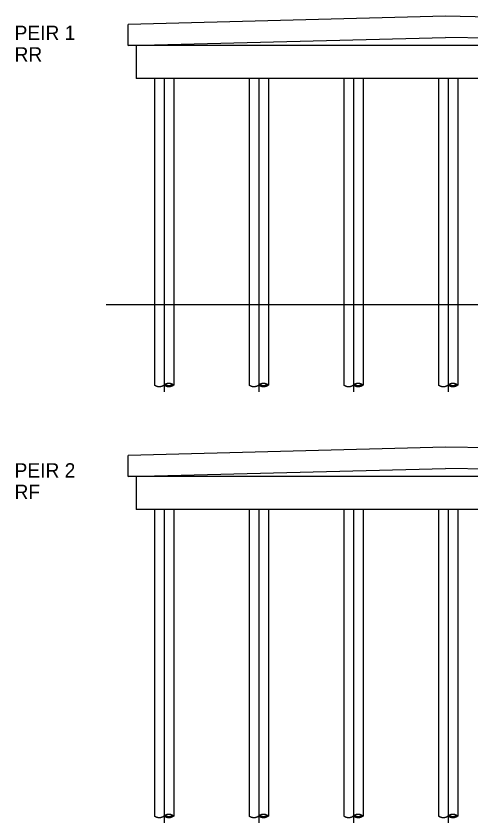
# Model space of a CAD drawing. Extents: x -8 to 159, y -47 to 10.
# Drawn here: x -7.56 to 20.06, y -47.01 to 1.94 of the extents above; entities that cross this region are included whole.
import ezdxf

# ---------------------------------------------------------------- set-up
doc = ezdxf.new("R2010")
doc.units = 0
for name, color, linetype in [('BR_X_Gen_Ground_Slope', 7, 'Continuous'), ('BR_X_Slab_Const_Joint', 7, 'Continuous'), ('BR_X_Slab_Object', 7, 'Continuous'), ('BR_X_Sub_Deep_Centerline', 7, 'Continuous'), ('BR_X_Sub_Object', 7, 'Continuous'), ('HY_P_Water_Edge', 7, 'Continuous')]:
    doc.layers.add(name, color=color, linetype=linetype)

msp = doc.modelspace()

# ---------------------------------------------------------------- linework, layer by layer
at = {"layer": 'BR_X_Gen_Ground_Slope'}
msp.add_line((1.427, -15.771), (1.427, -16.271), dxfattribs=at)
at = {"layer": 'BR_X_Slab_Const_Joint'}
for p, q in [((43.365, 0.146), (-0.26, 0.146)), ((43.365, -26), (-0.26, -26))]:
    msp.add_line(p, q, dxfattribs=at)
at = {"layer": 'BR_X_Slab_Object'}
for p, q in [((18.51, 1.937), (-0.76, 1.437)), ((43.865, 1.437), (18.51, 1.937)), ((-0.76, 0.146), (-0.76, 1.437)), ((-0.76, 0.146), (18.51, 0.646)), ((43.865, 0.146), (18.51, 0.646)), ((-0.26, 0.146), (-0.76, 0.146)), ((18.51, -24.208), (-0.76, -24.708)), ((43.865, -24.708), (18.51, -24.208)), ((-0.76, -26), (-0.76, -24.708)), ((-0.76, -26), (18.51, -25.5)), ((43.865, -26), (18.51, -25.5)), ((-0.26, -26), (-0.76, -26))]:
    msp.add_line(p, q, dxfattribs=at)
at = {"layer": 'BR_X_Sub_Deep_Centerline'}
for p, q in [((1.427, -1.854), (1.427, -20.859)), ((7.177, -1.854), (7.177, -20.859)), ((12.927, -1.854), (12.927, -20.859)), ((18.677, -1.854), (18.677, -20.859)), ((1.427, -28), (1.427, -47.005)), ((7.177, -28), (7.177, -47.005)), ((12.927, -28), (12.927, -47.005)), ((18.677, -28), (18.677, -47.005))]:
    msp.add_line(p, q, dxfattribs=at)
at = {"layer": 'BR_X_Sub_Object'}
for p, q in [((-0.26, 0.146), (-0.26, -1.854)), ((43.365, -1.854), (-0.26, -1.854)), ((0.844, -1.854), (0.844, -20.447)), ((2.011, -1.854), (2.011, -20.447)), ((6.594, -1.854), (6.594, -20.447)), ((7.761, -1.854), (7.761, -20.447)), ((12.344, -1.854), (12.344, -20.447)), ((13.511, -1.854), (13.511, -20.447)), ((18.094, -1.854), (18.094, -20.447)), ((19.261, -1.854), (19.261, -20.447)), ((-0.26, -26), (-0.26, -28)), ((43.365, -28), (-0.26, -28)), ((0.844, -28), (0.844, -46.593)), ((2.011, -28), (2.011, -46.593)), ((6.594, -28), (6.594, -46.593)), ((7.761, -28), (7.761, -46.593)), ((12.344, -28), (12.344, -46.593)), ((13.511, -28), (13.511, -46.593)), ((18.094, -28), (18.094, -46.593)), ((19.261, -28), (19.261, -46.593))]:
    msp.add_line(p, q, dxfattribs=at)
for points in [[(2.011, -20.447), (1.953, -20.407), (1.841, -20.361), (1.76, -20.347), (1.718, -20.345), (1.69, -20.346), (1.641, -20.352), (1.601, -20.36), (1.574, -20.368), (1.53, -20.385), (1.494, -20.402), (1.467, -20.419), (1.453, -20.428), (1.438, -20.439), (1.427, -20.447), (1.408, -20.463), (1.394, -20.473), (1.383, -20.48), (1.369, -20.489), (1.346, -20.502), (1.317, -20.516), (1.3, -20.523), (1.271, -20.533), (1.239, -20.542), (1.224, -20.545), (1.202, -20.549), (1.181, -20.552), (1.157, -20.554), (1.137, -20.554), (1.096, -20.552), (1.064, -20.548), (1.032, -20.542), (1.008, -20.536), (0.984, -20.528), (0.965, -20.52), (0.944, -20.511), (0.921, -20.5), (0.903, -20.49), (0.885, -20.478), (0.864, -20.463), (0.856, -20.457), (0.844, -20.447)], [(2.011, -20.447), (1.995, -20.46), (1.975, -20.475), (1.954, -20.488), (1.932, -20.501), (1.916, -20.509), (1.891, -20.52), (1.867, -20.529), (1.839, -20.538), (1.81, -20.545), (1.787, -20.549), (1.766, -20.552), (1.747, -20.553), (1.714, -20.554), (1.685, -20.554), (1.664, -20.551), (1.638, -20.547), (1.601, -20.538), (1.572, -20.529), (1.545, -20.519), (1.521, -20.508), (1.506, -20.5), (1.483, -20.487), (1.464, -20.475), (1.45, -20.465), (1.441, -20.458), (1.427, -20.447)], [(1.949, -20.41), (1.93, -20.424), (1.906, -20.438), (1.893, -20.445), (1.878, -20.453), (1.857, -20.462), (1.835, -20.469), (1.822, -20.474), (1.797, -20.48), (1.783, -20.483), (1.763, -20.486), (1.741, -20.488), (1.716, -20.489), (1.723, -20.489), (1.705, -20.489), (1.692, -20.488), (1.669, -20.486), (1.64, -20.482), (1.623, -20.478), (1.602, -20.472), (1.588, -20.468), (1.568, -20.46), (1.557, -20.456), (1.548, -20.451), (1.537, -20.446), (1.525, -20.439), (1.514, -20.433), (1.496, -20.422), (1.491, -20.418), (1.481, -20.41)], [(7.761, -20.447), (7.703, -20.407), (7.591, -20.361), (7.51, -20.347), (7.468, -20.345), (7.44, -20.346), (7.391, -20.352), (7.351, -20.36), (7.324, -20.368), (7.28, -20.385), (7.244, -20.402), (7.217, -20.419), (7.203, -20.428), (7.188, -20.439), (7.177, -20.447), (7.158, -20.463), (7.144, -20.473), (7.133, -20.48), (7.119, -20.489), (7.096, -20.502), (7.067, -20.516), (7.05, -20.523), (7.021, -20.533), (6.989, -20.542), (6.974, -20.545), (6.952, -20.549), (6.931, -20.552), (6.907, -20.554), (6.887, -20.554), (6.846, -20.552), (6.814, -20.548), (6.782, -20.542), (6.758, -20.536), (6.734, -20.528), (6.715, -20.52), (6.694, -20.511), (6.671, -20.5), (6.653, -20.49), (6.635, -20.478), (6.614, -20.463), (6.606, -20.457), (6.594, -20.447)], [(7.761, -20.447), (7.745, -20.46), (7.725, -20.475), (7.704, -20.488), (7.682, -20.501), (7.666, -20.509), (7.641, -20.52), (7.617, -20.529), (7.589, -20.538), (7.56, -20.545), (7.537, -20.549), (7.516, -20.552), (7.497, -20.553), (7.464, -20.554), (7.435, -20.554), (7.414, -20.551), (7.388, -20.547), (7.351, -20.538), (7.322, -20.529), (7.295, -20.519), (7.271, -20.508), (7.256, -20.5), (7.233, -20.487), (7.214, -20.475), (7.2, -20.465), (7.191, -20.458), (7.177, -20.447)], [(7.699, -20.41), (7.68, -20.424), (7.656, -20.438), (7.643, -20.445), (7.628, -20.453), (7.607, -20.462), (7.585, -20.469), (7.572, -20.474), (7.547, -20.48), (7.533, -20.483), (7.513, -20.486), (7.491, -20.488), (7.466, -20.489), (7.473, -20.489), (7.455, -20.489), (7.442, -20.488), (7.419, -20.486), (7.39, -20.482), (7.373, -20.478), (7.352, -20.472), (7.338, -20.468), (7.318, -20.46), (7.307, -20.456), (7.298, -20.451), (7.287, -20.446), (7.275, -20.439), (7.264, -20.433), (7.246, -20.422), (7.241, -20.418), (7.231, -20.41)], [(13.511, -20.447), (13.453, -20.407), (13.341, -20.361), (13.26, -20.347), (13.218, -20.345), (13.19, -20.346), (13.141, -20.352), (13.101, -20.36), (13.074, -20.368), (13.03, -20.385), (12.994, -20.402), (12.967, -20.419), (12.953, -20.428), (12.938, -20.439), (12.927, -20.447), (12.908, -20.463), (12.894, -20.473), (12.883, -20.48), (12.869, -20.489), (12.846, -20.502), (12.817, -20.516), (12.8, -20.523), (12.771, -20.533), (12.739, -20.542), (12.724, -20.545), (12.702, -20.549), (12.681, -20.552), (12.657, -20.554), (12.637, -20.554), (12.596, -20.552), (12.564, -20.548), (12.532, -20.542), (12.508, -20.536), (12.484, -20.528), (12.465, -20.52), (12.444, -20.511), (12.421, -20.5), (12.403, -20.49), (12.385, -20.478), (12.364, -20.463), (12.356, -20.457), (12.344, -20.447)], [(13.511, -20.447), (13.495, -20.46), (13.475, -20.475), (13.454, -20.488), (13.432, -20.501), (13.416, -20.509), (13.391, -20.52), (13.367, -20.529), (13.339, -20.538), (13.31, -20.545), (13.287, -20.549), (13.266, -20.552), (13.247, -20.553), (13.214, -20.554), (13.185, -20.554), (13.164, -20.551), (13.138, -20.547), (13.101, -20.538), (13.072, -20.529), (13.045, -20.519), (13.021, -20.508), (13.006, -20.5), (12.983, -20.487), (12.964, -20.475), (12.95, -20.465), (12.941, -20.458), (12.927, -20.447)], [(13.449, -20.41), (13.43, -20.424), (13.406, -20.438), (13.393, -20.445), (13.378, -20.453), (13.357, -20.462), (13.335, -20.469), (13.322, -20.474), (13.297, -20.48), (13.283, -20.483), (13.263, -20.486), (13.241, -20.488), (13.216, -20.489), (13.223, -20.489), (13.205, -20.489), (13.192, -20.488), (13.169, -20.486), (13.14, -20.482), (13.123, -20.478), (13.102, -20.472), (13.088, -20.468), (13.068, -20.46), (13.057, -20.456), (13.048, -20.451), (13.037, -20.446), (13.025, -20.439), (13.014, -20.433), (12.996, -20.422), (12.991, -20.418), (12.981, -20.41)], [(19.261, -20.447), (19.203, -20.407), (19.091, -20.361), (19.01, -20.347), (18.968, -20.345), (18.94, -20.346), (18.891, -20.352), (18.851, -20.36), (18.824, -20.368), (18.78, -20.385), (18.744, -20.402), (18.717, -20.419), (18.703, -20.428), (18.688, -20.439), (18.677, -20.447), (18.658, -20.463), (18.644, -20.473), (18.633, -20.48), (18.619, -20.489), (18.596, -20.502), (18.567, -20.516), (18.55, -20.523), (18.521, -20.533), (18.489, -20.542), (18.474, -20.545), (18.452, -20.549), (18.431, -20.552), (18.407, -20.554), (18.387, -20.554), (18.346, -20.552), (18.314, -20.548), (18.282, -20.542), (18.258, -20.536), (18.234, -20.528), (18.215, -20.52), (18.194, -20.511), (18.171, -20.5), (18.153, -20.49), (18.135, -20.478), (18.114, -20.463), (18.106, -20.457), (18.094, -20.447)], [(19.261, -20.447), (19.245, -20.46), (19.225, -20.475), (19.204, -20.488), (19.182, -20.501), (19.166, -20.509), (19.141, -20.52), (19.117, -20.529), (19.089, -20.538), (19.06, -20.545), (19.037, -20.549), (19.016, -20.552), (18.997, -20.553), (18.964, -20.554), (18.935, -20.554), (18.914, -20.551), (18.888, -20.547), (18.851, -20.538), (18.822, -20.529), (18.795, -20.519), (18.771, -20.508), (18.756, -20.5), (18.733, -20.487), (18.714, -20.475), (18.7, -20.465), (18.691, -20.458), (18.677, -20.447)], [(19.199, -20.41), (19.18, -20.424), (19.156, -20.438), (19.143, -20.445), (19.128, -20.453), (19.107, -20.462), (19.085, -20.469), (19.072, -20.474), (19.047, -20.48), (19.033, -20.483), (19.013, -20.486), (18.991, -20.488), (18.966, -20.489), (18.973, -20.489), (18.955, -20.489), (18.942, -20.488), (18.919, -20.486), (18.89, -20.482), (18.873, -20.478), (18.852, -20.472), (18.838, -20.468), (18.818, -20.46), (18.807, -20.456), (18.798, -20.451), (18.787, -20.446), (18.775, -20.439), (18.764, -20.433), (18.746, -20.422), (18.741, -20.418), (18.731, -20.41)], [(2.011, -46.593), (1.953, -46.553), (1.841, -46.507), (1.76, -46.492), (1.718, -46.491), (1.69, -46.492), (1.641, -46.497), (1.601, -46.506), (1.574, -46.514), (1.53, -46.531), (1.494, -46.548), (1.467, -46.565), (1.453, -46.574), (1.438, -46.585), (1.427, -46.592), (1.408, -46.609), (1.394, -46.618), (1.383, -46.626), (1.369, -46.635), (1.346, -46.648), (1.317, -46.662), (1.3, -46.669), (1.271, -46.679), (1.239, -46.688), (1.224, -46.691), (1.202, -46.695), (1.181, -46.698), (1.157, -46.699), (1.137, -46.7), (1.096, -46.698), (1.064, -46.694), (1.032, -46.688), (1.008, -46.681), (0.984, -46.673), (0.965, -46.666), (0.944, -46.657), (0.921, -46.645), (0.903, -46.635), (0.885, -46.624), (0.864, -46.609), (0.856, -46.602), (0.844, -46.593)], [(7.761, -46.593), (7.703, -46.553), (7.591, -46.507), (7.51, -46.492), (7.468, -46.491), (7.44, -46.492), (7.391, -46.497), (7.351, -46.506), (7.324, -46.514), (7.28, -46.531), (7.244, -46.548), (7.217, -46.565), (7.203, -46.574), (7.188, -46.585), (7.177, -46.592), (7.158, -46.609), (7.144, -46.618), (7.133, -46.626), (7.119, -46.635), (7.096, -46.648), (7.067, -46.662), (7.05, -46.669), (7.021, -46.679), (6.989, -46.688), (6.974, -46.691), (6.952, -46.695), (6.931, -46.698), (6.907, -46.699), (6.887, -46.7), (6.846, -46.698), (6.814, -46.694), (6.782, -46.688), (6.758, -46.681), (6.734, -46.673), (6.715, -46.666), (6.694, -46.657), (6.671, -46.645), (6.653, -46.635), (6.635, -46.624), (6.614, -46.609), (6.606, -46.602), (6.594, -46.593)], [(13.511, -46.593), (13.453, -46.553), (13.341, -46.507), (13.26, -46.492), (13.218, -46.491), (13.19, -46.492), (13.141, -46.497), (13.101, -46.506), (13.074, -46.514), (13.03, -46.531), (12.994, -46.548), (12.967, -46.565), (12.953, -46.574), (12.938, -46.585), (12.927, -46.592), (12.908, -46.609), (12.894, -46.618), (12.883, -46.626), (12.869, -46.635), (12.846, -46.648), (12.817, -46.662), (12.8, -46.669), (12.771, -46.679), (12.739, -46.688), (12.724, -46.691), (12.702, -46.695), (12.681, -46.698), (12.657, -46.699), (12.637, -46.7), (12.596, -46.698), (12.564, -46.694), (12.532, -46.688), (12.508, -46.681), (12.484, -46.673), (12.465, -46.666), (12.444, -46.657), (12.421, -46.645), (12.403, -46.635), (12.385, -46.624), (12.364, -46.609), (12.356, -46.602), (12.344, -46.593)], [(19.261, -46.593), (19.203, -46.553), (19.091, -46.507), (19.01, -46.492), (18.968, -46.491), (18.94, -46.492), (18.891, -46.497), (18.851, -46.506), (18.824, -46.514), (18.78, -46.531), (18.744, -46.548), (18.717, -46.565), (18.703, -46.574), (18.688, -46.585), (18.677, -46.592), (18.658, -46.609), (18.644, -46.618), (18.633, -46.626), (18.619, -46.635), (18.596, -46.648), (18.567, -46.662), (18.55, -46.669), (18.521, -46.679), (18.489, -46.688), (18.474, -46.691), (18.452, -46.695), (18.431, -46.698), (18.407, -46.699), (18.387, -46.7), (18.346, -46.698), (18.314, -46.694), (18.282, -46.688), (18.258, -46.681), (18.234, -46.673), (18.215, -46.666), (18.194, -46.657), (18.171, -46.645), (18.153, -46.635), (18.135, -46.624), (18.114, -46.609), (18.106, -46.602), (18.094, -46.593)], [(2.011, -46.593), (1.995, -46.605), (1.975, -46.62), (1.954, -46.634), (1.932, -46.646), (1.916, -46.655), (1.891, -46.666), (1.867, -46.675), (1.839, -46.684), (1.81, -46.691), (1.787, -46.695), (1.766, -46.697), (1.747, -46.699), (1.714, -46.7), (1.685, -46.7), (1.664, -46.696), (1.638, -46.692), (1.601, -46.684), (1.572, -46.675), (1.545, -46.665), (1.521, -46.654), (1.506, -46.646), (1.483, -46.633), (1.464, -46.621), (1.45, -46.61), (1.441, -46.604), (1.427, -46.593)], [(1.949, -46.556), (1.93, -46.57), (1.906, -46.584), (1.893, -46.591), (1.878, -46.599), (1.857, -46.608), (1.835, -46.615), (1.822, -46.62), (1.797, -46.626), (1.783, -46.629), (1.763, -46.632), (1.741, -46.634), (1.716, -46.635), (1.723, -46.634), (1.705, -46.634), (1.692, -46.634), (1.669, -46.632), (1.64, -46.627), (1.623, -46.624), (1.602, -46.618), (1.588, -46.613), (1.568, -46.606), (1.557, -46.601), (1.548, -46.597), (1.537, -46.592), (1.525, -46.585), (1.514, -46.579), (1.496, -46.568), (1.491, -46.564), (1.481, -46.556)], [(7.761, -46.593), (7.745, -46.605), (7.725, -46.62), (7.704, -46.634), (7.682, -46.646), (7.666, -46.655), (7.641, -46.666), (7.617, -46.675), (7.589, -46.684), (7.56, -46.691), (7.537, -46.695), (7.516, -46.697), (7.497, -46.699), (7.464, -46.7), (7.435, -46.7), (7.414, -46.696), (7.388, -46.692), (7.351, -46.684), (7.322, -46.675), (7.295, -46.665), (7.271, -46.654), (7.256, -46.646), (7.233, -46.633), (7.214, -46.621), (7.2, -46.61), (7.191, -46.604), (7.177, -46.593)], [(7.699, -46.556), (7.68, -46.57), (7.656, -46.584), (7.643, -46.591), (7.628, -46.599), (7.607, -46.608), (7.585, -46.615), (7.572, -46.62), (7.547, -46.626), (7.533, -46.629), (7.513, -46.632), (7.491, -46.634), (7.466, -46.635), (7.473, -46.634), (7.455, -46.634), (7.442, -46.634), (7.419, -46.632), (7.39, -46.627), (7.373, -46.624), (7.352, -46.618), (7.338, -46.613), (7.318, -46.606), (7.307, -46.601), (7.298, -46.597), (7.287, -46.592), (7.275, -46.585), (7.264, -46.579), (7.246, -46.568), (7.241, -46.564), (7.231, -46.556)], [(13.511, -46.593), (13.495, -46.605), (13.475, -46.62), (13.454, -46.634), (13.432, -46.646), (13.416, -46.655), (13.391, -46.666), (13.367, -46.675), (13.339, -46.684), (13.31, -46.691), (13.287, -46.695), (13.266, -46.697), (13.247, -46.699), (13.214, -46.7), (13.185, -46.7), (13.164, -46.696), (13.138, -46.692), (13.101, -46.684), (13.072, -46.675), (13.045, -46.665), (13.021, -46.654), (13.006, -46.646), (12.983, -46.633), (12.964, -46.621), (12.95, -46.61), (12.941, -46.604), (12.927, -46.593)], [(13.449, -46.556), (13.43, -46.57), (13.406, -46.584), (13.393, -46.591), (13.378, -46.599), (13.357, -46.608), (13.335, -46.615), (13.322, -46.62), (13.297, -46.626), (13.283, -46.629), (13.263, -46.632), (13.241, -46.634), (13.216, -46.635), (13.223, -46.634), (13.205, -46.634), (13.192, -46.634), (13.169, -46.632), (13.14, -46.627), (13.123, -46.624), (13.102, -46.618), (13.088, -46.613), (13.068, -46.606), (13.057, -46.601), (13.048, -46.597), (13.037, -46.592), (13.025, -46.585), (13.014, -46.579), (12.996, -46.568), (12.991, -46.564), (12.981, -46.556)], [(19.261, -46.593), (19.245, -46.605), (19.225, -46.62), (19.204, -46.634), (19.182, -46.646), (19.166, -46.655), (19.141, -46.666), (19.117, -46.675), (19.089, -46.684), (19.06, -46.691), (19.037, -46.695), (19.016, -46.697), (18.997, -46.699), (18.964, -46.7), (18.935, -46.7), (18.914, -46.696), (18.888, -46.692), (18.851, -46.684), (18.822, -46.675), (18.795, -46.665), (18.771, -46.654), (18.756, -46.646), (18.733, -46.633), (18.714, -46.621), (18.7, -46.61), (18.691, -46.604), (18.677, -46.593)], [(19.199, -46.556), (19.18, -46.57), (19.156, -46.584), (19.143, -46.591), (19.128, -46.599), (19.107, -46.608), (19.085, -46.615), (19.072, -46.62), (19.047, -46.626), (19.033, -46.629), (19.013, -46.632), (18.991, -46.634), (18.966, -46.635), (18.973, -46.634), (18.955, -46.634), (18.942, -46.634), (18.919, -46.632), (18.89, -46.627), (18.873, -46.624), (18.852, -46.618), (18.838, -46.613), (18.818, -46.606), (18.807, -46.601), (18.798, -46.597), (18.787, -46.592), (18.775, -46.585), (18.764, -46.579), (18.746, -46.568), (18.741, -46.564), (18.731, -46.556)]]:
    msp.add_open_spline(points, degree=2, dxfattribs=at)
at = {"layer": 'HY_P_Water_Edge'}
msp.add_line((47.677, -15.574), (-2.09, -15.574), dxfattribs=at)

# ---------------------------------------------------------------- texts
at = {"layer": 'BR_X_Slab_Object'}
for s, p in [('PEIR 1', (-7.655, 0.487)), ('RR', (-7.655, -0.82)), ('PEIR 2', (-7.655, -26.056)), ('RF', (-7.655, -27.363))]:
    msp.add_text(s, height=0.8714, dxfattribs=at).set_placement(p)

doc.saveas('drawing.dxf')
